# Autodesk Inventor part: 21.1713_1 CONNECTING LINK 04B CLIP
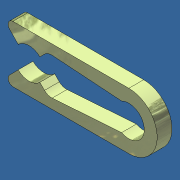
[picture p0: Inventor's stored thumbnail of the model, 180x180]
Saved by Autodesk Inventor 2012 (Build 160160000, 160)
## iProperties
Created: 2016-02
Part Number: 21.1713_1 CONNECTING LINK 04B CLIP
Material: Steel
Document SubType Name: Modeling
Designer: Admin
Density: 7.85 g/cm^3
Mass: 0.0990961 g
Surface Area: 0.630902 cm^2
Volume: 0.0126237 cm^3
Author: Admin
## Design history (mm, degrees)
feature "Base1"
body "Solid1"
